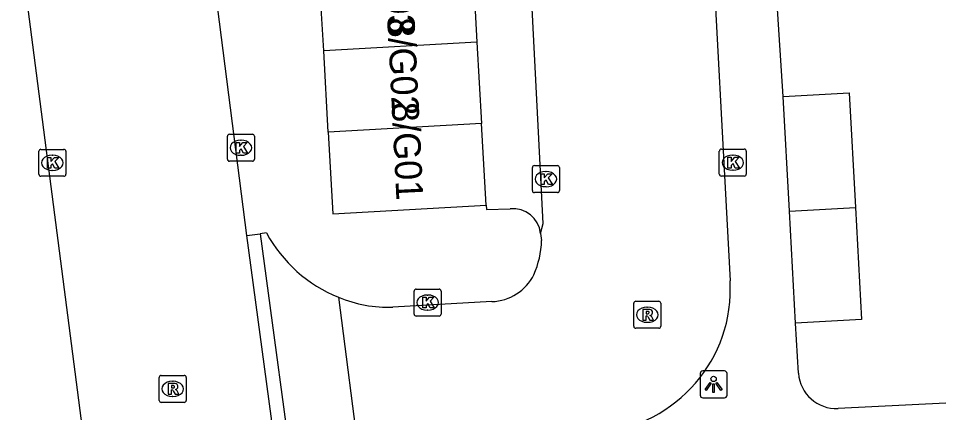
# Model space of a CAD drawing. Extents: x 161084 to 161928, y 385355 to 386522.
# Drawn here: x 161311.4 to 161345.53, y 385480.77 to 385495.38 of the extents above; entities that cross this region are included whole.
import ezdxf

# ---------------------------------------------------------------- set-up
doc = ezdxf.new("R2010")
doc.units = 0
for name, color, linetype in [('IMGEO_Kolk', 7, 'Continuous'), ('IMGEO_Lichtpunt', 7, 'Continuous'), ('IMGEO_Pand', 7, 'Continuous'), ('IMGEO_Pand_nummerreeks', 7, 'Continuous'), ('IMGEO_Rijbaan_lokaal_open', 7, 'Continuous'), ('IMGEO_Rioolput', 7, 'Continuous'), ('IMGEO_Voetpad_open', 7, 'Continuous')]:
    doc.layers.add(name, color=color, linetype=linetype)

msp = doc.modelspace()

# ---------------------------------------------------------------- linework, layer by layer
at = {"layer": 'IMGEO_Kolk'}
for p, q in [((161319.152, 385490.161), (161319.152, 385491.013)), ((161319.227, 385491.087), (161320.079, 385491.087)), ((161320.153, 385491.013), (161320.153, 385490.161)), ((161319.64, 385490.867), (161319.665, 385490.867)), ((161312.159, 385489.602), (161312.159, 385490.454)), ((161312.234, 385490.528), (161313.086, 385490.528)), ((161312.647, 385490.308), (161312.672, 385490.308)), ((161313.16, 385490.454), (161313.16, 385489.602)), ((161319.663, 385490.307), (161319.638, 385490.307)), ((161337.399, 385489.608), (161337.399, 385490.46)), ((161337.474, 385490.534), (161338.326, 385490.534)), ((161337.887, 385490.314), (161337.912, 385490.314)), ((161338.4, 385490.46), (161338.4, 385489.608)), ((161320.079, 385490.087), (161319.227, 385490.087)), ((161330.539, 385489.924), (161331.391, 385489.924)), ((161312.67, 385489.748), (161312.645, 385489.748)), ((161330.464, 385488.998), (161330.464, 385489.85)), ((161330.952, 385489.704), (161330.977, 385489.704)), ((161331.465, 385489.85), (161331.465, 385488.998)), ((161337.91, 385489.754), (161337.885, 385489.754)), ((161313.086, 385489.528), (161312.234, 385489.528)), ((161338.326, 385489.534), (161337.474, 385489.534)), ((161331.391, 385488.924), (161330.539, 385488.924)), ((161330.975, 385489.144), (161330.95, 385489.144)), ((161326.077, 385484.422), (161326.077, 385485.274)), ((161326.152, 385485.348), (161327.004, 385485.348)), ((161326.565, 385485.128), (161326.59, 385485.128)), ((161327.078, 385485.274), (161327.078, 385484.422)), ((161326.588, 385484.568), (161326.563, 385484.568)), ((161327.004, 385484.348), (161326.152, 385484.348))]:
    msp.add_line(p, q, dxfattribs=at)
for points in [[(161319.152, 385490.161), (161319.152, 385491.013)], [(161319.227, 385491.087), (161320.079, 385491.087)], [(161320.153, 385491.013), (161320.153, 385490.161)], [(161319.473, 385490.787), (161319.596, 385490.787), (161319.596, 385490.636), (161319.726, 385490.787), (161319.89, 385490.787), (161319.744, 385490.636), (161319.897, 385490.387), (161319.745, 385490.387), (161319.66, 385490.551), (161319.596, 385490.484), (161319.596, 385490.387), (161319.473, 385490.387), (161319.473, 385490.787)], [(161312.159, 385489.602), (161312.159, 385490.454)], [(161312.234, 385490.528), (161313.086, 385490.528)], [(161313.16, 385490.454), (161313.16, 385489.602)], [(161337.399, 385489.608), (161337.399, 385490.46)], [(161337.474, 385490.534), (161338.326, 385490.534)], [(161337.72, 385490.234), (161337.843, 385490.234), (161337.843, 385490.083), (161337.973, 385490.234), (161338.137, 385490.234), (161337.991, 385490.083), (161338.144, 385489.834), (161337.992, 385489.834), (161337.907, 385489.998), (161337.843, 385489.931), (161337.843, 385489.834), (161337.72, 385489.834), (161337.72, 385490.234)], [(161338.4, 385490.46), (161338.4, 385489.608)], [(161312.48, 385490.228), (161312.603, 385490.228), (161312.603, 385490.077), (161312.733, 385490.228), (161312.897, 385490.228), (161312.751, 385490.077), (161312.904, 385489.828), (161312.752, 385489.828), (161312.667, 385489.992), (161312.603, 385489.925), (161312.603, 385489.828), (161312.48, 385489.828), (161312.48, 385490.228)], [(161320.079, 385490.087), (161319.227, 385490.087)], [(161330.539, 385489.924), (161331.391, 385489.924)], [(161330.464, 385488.998), (161330.464, 385489.85)], [(161330.785, 385489.624), (161330.908, 385489.624), (161330.908, 385489.473), (161331.038, 385489.624), (161331.202, 385489.624), (161331.056, 385489.473), (161331.209, 385489.224), (161331.057, 385489.224), (161330.972, 385489.388), (161330.908, 385489.321), (161330.908, 385489.224), (161330.785, 385489.224), (161330.785, 385489.624)], [(161331.465, 385489.85), (161331.465, 385488.998)], [(161313.086, 385489.528), (161312.234, 385489.528)], [(161338.326, 385489.534), (161337.474, 385489.534)], [(161331.391, 385488.924), (161330.539, 385488.924)], [(161326.077, 385484.422), (161326.077, 385485.274)], [(161326.152, 385485.348), (161327.004, 385485.348)], [(161327.078, 385485.274), (161327.078, 385484.422)], [(161326.398, 385485.048), (161326.521, 385485.048), (161326.521, 385484.897), (161326.651, 385485.048), (161326.815, 385485.048), (161326.669, 385484.897), (161326.822, 385484.648), (161326.67, 385484.648), (161326.585, 385484.812), (161326.521, 385484.745), (161326.521, 385484.648), (161326.398, 385484.648), (161326.398, 385485.048)], [(161327.004, 385484.348), (161326.152, 385484.348)]]:
    msp.add_lwpolyline(points, dxfattribs=at)
for centre, start, end in [((161319.229, 385491.011), 91.552, 178.448), ((161319.229, 385491.011), 91.552, 178.448), ((161320.077, 385491.011), 1.552, 88.448), ((161320.077, 385491.011), 1.552, 88.448), ((161312.236, 385490.452), 91.552, 178.448), ((161312.236, 385490.452), 91.552, 178.448), ((161313.084, 385490.452), 1.552, 88.448), ((161313.084, 385490.452), 1.552, 88.448), ((161337.476, 385490.458), 91.552, 178.448), ((161337.476, 385490.458), 91.552, 178.448), ((161338.324, 385490.458), 1.552, 88.448), ((161338.324, 385490.458), 1.552, 88.448), ((161319.229, 385490.163), 181.552, 268.448), ((161319.229, 385490.163), 181.552, 268.448), ((161320.077, 385490.163), 271.552, 358.448), ((161320.077, 385490.163), 271.552, 358.448), ((161330.541, 385489.848), 91.552, 178.448), ((161330.541, 385489.848), 91.552, 178.448), ((161331.389, 385489.848), 1.552, 88.448), ((161331.389, 385489.848), 1.552, 88.448), ((161312.236, 385489.604), 181.552, 268.448), ((161312.236, 385489.604), 181.552, 268.448), ((161313.084, 385489.604), 271.552, 358.448), ((161313.084, 385489.604), 271.552, 358.448), ((161337.476, 385489.61), 181.552, 268.448), ((161337.476, 385489.61), 181.552, 268.448), ((161338.324, 385489.61), 271.552, 358.448), ((161338.324, 385489.61), 271.552, 358.448), ((161330.541, 385489), 181.552, 268.448), ((161330.541, 385489), 181.552, 268.448), ((161331.389, 385489), 271.552, 358.448), ((161331.389, 385489), 271.552, 358.448), ((161326.154, 385485.272), 91.552, 178.448), ((161326.154, 385485.272), 91.552, 178.448), ((161327.002, 385485.272), 1.552, 88.448), ((161327.002, 385485.272), 1.552, 88.448), ((161326.154, 385484.424), 181.552, 268.448), ((161326.154, 385484.424), 181.552, 268.448), ((161327.002, 385484.424), 271.552, 358.448), ((161327.002, 385484.424), 271.552, 358.448)]:
    msp.add_arc(centre, 0.0765, start, end, dxfattribs=at)
for centre, major_axis, ratio, start_param, end_param in [((161319.639, 385490.587), (-0.387, 0.002), 0.722429, 4.712389, 7.853982), ((161319.664, 385490.587), (-0.39, 0.002), 0.717154, 1.570796, 4.712389), ((161312.646, 385490.028), (-0.387, 0.002), 0.722429, 4.712389, 7.853982), ((161312.671, 385490.028), (-0.39, 0.002), 0.717154, 1.570796, 4.712389), ((161337.886, 385490.034), (-0.387, 0.002), 0.722429, 4.712389, 7.853982), ((161337.911, 385490.034), (-0.39, 0.002), 0.717154, 1.570796, 4.712389), ((161330.951, 385489.424), (-0.387, 0.002), 0.722429, 4.712389, 7.853982), ((161330.976, 385489.424), (-0.39, 0.002), 0.717154, 1.570796, 4.712389), ((161326.564, 385484.848), (-0.387, 0.002), 0.722429, 4.712389, 7.853982), ((161326.589, 385484.848), (-0.39, 0.002), 0.717154, 1.570796, 4.712389)]:
    msp.add_ellipse(centre, major_axis=major_axis, ratio=ratio, start_param=start_param, end_param=end_param, dxfattribs=at)
at = {"layer": 'IMGEO_Lichtpunt'}
for p, q in [((161336.688, 385482.22), (161336.688, 385481.413)), ((161336.688, 385482.22), (161336.688, 385481.413)), ((161337.59, 385482.315), (161336.782, 385482.315)), ((161337.59, 385482.315), (161336.782, 385482.315)), ((161337.684, 385481.413), (161337.684, 385482.22)), ((161337.684, 385481.413), (161337.684, 385482.22)), ((161336.782, 385481.319), (161337.59, 385481.319)), ((161336.782, 385481.319), (161337.59, 385481.319))]:
    msp.add_line(p, q, dxfattribs=at)
for points in [[(161337.062, 385481.884), (161337.101, 385481.856), (161336.913, 385481.594), (161336.875, 385481.621), (161337.062, 385481.884)], [(161337.164, 385481.836), (161337.211, 385481.836), (161337.211, 385481.514), (161337.164, 385481.514), (161337.164, 385481.836)], [(161337.274, 385481.856), (161337.312, 385481.883), (161337.499, 385481.621), (161337.46, 385481.593), (161337.274, 385481.856)]]:
    msp.add_lwpolyline(points, dxfattribs=at)
msp.add_circle((161337.187, 385482.018), 0.0994, dxfattribs=at)
for centre, start, end in [((161336.782, 385482.22), 90, 180), ((161336.782, 385482.22), 90, 180), ((161337.59, 385482.22), 0, 90), ((161337.59, 385482.22), 0, 90), ((161336.782, 385481.413), 180, 270), ((161336.782, 385481.413), 180, 270), ((161337.59, 385481.413), 270, 0), ((161337.59, 385481.413), 270, 360)]:
    msp.add_arc(centre, 0.0946, start, end, dxfattribs=at)
at = {"layer": 'IMGEO_Pand'}
for points in [[(161328.238, 385497.524), (161328.409, 385494.502)], [(161322.723, 385494.18), (161322.622, 385495.956)], [(161328.409, 385494.502), (161322.723, 385494.18)], [(161328.409, 385494.502), (161328.58, 385491.48)], [(161322.896, 385491.159), (161322.723, 385494.18)], [(161339.771, 385492.485), (161342.219, 385492.618), (161342.45, 385488.367)], [(161340.002, 385488.233), (161339.771, 385492.485)], [(161328.58, 385491.48), (161322.896, 385491.159)], [(161328.751, 385488.458), (161328.58, 385491.48)], [(161322.896, 385491.159), (161323.068, 385488.134), (161328.751, 385488.458)], [(161340.002, 385488.233), (161342.45, 385488.367)], [(161340.227, 385484.085), (161340.002, 385488.233)], [(161342.45, 385488.367), (161342.675, 385484.218), (161340.227, 385484.085)]]:
    msp.add_lwpolyline(points, dxfattribs=at)
at = {"layer": 'IMGEO_Rijbaan_lokaal_open'}
for points in [[(161335.42, 385532.391), (161337.024, 385500.143), (161337.796, 385485.654)], [(161330.768, 385487.413), (161330.865, 385487.775), (161328.687, 385530.316), (161328.582, 385530.386)], [(161319.868, 385487.335), (161318.329, 385499.414)], [(161315.293, 385468.442), (161311.4, 385498.51)], [(161321.269, 385476.973), (161319.868, 385487.335)], [(161320.606, 385487.429), (161320.363, 385487.4)], [(161320.363, 385487.4), (161321.764, 385477.038)], [(161330.768, 385487.413), (161330.809, 385487.145)], [(161323.275, 385485.049), (161324.075, 385478.793)], [(161328.966, 385484.883), (161325.294, 385484.679)]]:
    msp.add_lwpolyline(points, dxfattribs=at)
for centre, radius, start, end in [((161325.199, 385489.894), 5.213, 208.2161, 248.3358), ((161327.198, 385487.298), 3.614, 336.9229, 357.5783), ((161328.897, 385486.705), 1.823, 272.1835, 333.1343), ((161332.497, 385485.334), 5.309, 274.8736, 3.4611), ((161325.114, 385489.39), 4.714, 247.0411, 272.1895)]:
    msp.add_arc(centre, radius, start, end, dxfattribs=at)
at = {"layer": 'IMGEO_Rioolput'}
for p, q in [((161334.227, 385483.97), (161334.227, 385484.822)), ((161334.302, 385484.896), (161335.154, 385484.896)), ((161335.228, 385484.822), (161335.228, 385483.97)), ((161334.715, 385484.676), (161334.74, 385484.676)), ((161334.738, 385484.116), (161334.713, 385484.116)), ((161335.154, 385483.896), (161334.302, 385483.896)), ((161316.623, 385481.224), (161316.623, 385482.076)), ((161316.698, 385482.15), (161317.55, 385482.15)), ((161317.624, 385482.076), (161317.624, 385481.224)), ((161317.111, 385481.93), (161317.136, 385481.93)), ((161317.134, 385481.37), (161317.109, 385481.37)), ((161317.55, 385481.15), (161316.698, 385481.15))]:
    msp.add_line(p, q, dxfattribs=at)
for points in [[(161334.227, 385483.97), (161334.227, 385484.822)], [(161334.302, 385484.896), (161335.154, 385484.896)], [(161335.228, 385484.822), (161335.228, 385483.97)], [(161334.816, 385484.594), (161334.564, 385484.596), (161334.564, 385484.196)], [(161334.742, 385484.515), (161334.688, 385484.515), (161334.688, 385484.434)], [(161334.688, 385484.434), (161334.74, 385484.434)], [(161334.564, 385484.196), (161334.688, 385484.196), (161334.688, 385484.358), (161334.699, 385484.358)], [(161334.746, 385484.329), (161334.817, 385484.196), (161334.957, 385484.196), (161334.892, 385484.322)], [(161335.154, 385483.896), (161334.302, 385483.896)], [(161316.623, 385481.224), (161316.623, 385482.076)], [(161316.698, 385482.15), (161317.55, 385482.15)], [(161317.624, 385482.076), (161317.624, 385481.224)], [(161317.212, 385481.848), (161316.96, 385481.85), (161316.96, 385481.45)], [(161317.138, 385481.769), (161317.084, 385481.769), (161317.084, 385481.688)], [(161316.96, 385481.45), (161317.084, 385481.45), (161317.084, 385481.612), (161317.095, 385481.612)], [(161317.084, 385481.688), (161317.136, 385481.688)], [(161317.142, 385481.583), (161317.213, 385481.45), (161317.353, 385481.45), (161317.288, 385481.576)], [(161317.55, 385481.15), (161316.698, 385481.15)]]:
    msp.add_lwpolyline(points, dxfattribs=at)
for centre, radius, start, end in [((161334.304, 385484.82), 0.0765, 91.552, 178.448), ((161334.304, 385484.82), 0.0765, 91.552, 178.448), ((161335.152, 385484.82), 0.0765, 1.552, 88.448), ((161335.152, 385484.82), 0.0765, 1.552, 88.448), ((161334.724, 385484.623), 0.19, 274.7715, 282.9687), ((161334.748, 385484.419), 0.0964, 77.0061, 93.1865), ((161334.762, 385484.476), 0.0378, 276.6634, 79.6772), ((161334.815, 385484.484), 0.109, 350.3612, 89.416), ((161334.813, 385484.484), 0.112, 277.5842, 350.9817), ((161334.698, 385484.305), 0.0533, 26.0293, 88.6989), ((161334.797, 385484.269), 0.108, 29.5134, 73.7905), ((161334.304, 385483.972), 0.0765, 181.552, 268.448), ((161334.304, 385483.972), 0.0765, 181.552, 268.448), ((161335.152, 385483.972), 0.0765, 271.552, 358.448), ((161335.152, 385483.972), 0.0765, 271.552, 358.448), ((161316.7, 385482.074), 0.0765, 91.552, 178.448), ((161316.7, 385482.074), 0.0765, 91.552, 178.448), ((161317.548, 385482.074), 0.0765, 1.552, 88.448), ((161317.548, 385482.074), 0.0765, 1.552, 88.448), ((161317.144, 385481.673), 0.0964, 77.0061, 93.1865), ((161317.158, 385481.73), 0.0378, 276.6634, 79.6772), ((161317.211, 385481.738), 0.109, 350.3612, 89.416), ((161317.209, 385481.738), 0.112, 277.5842, 350.9817), ((161317.094, 385481.559), 0.0533, 26.0293, 88.6989), ((161317.12, 385481.877), 0.19, 274.7715, 282.9687), ((161317.193, 385481.523), 0.108, 29.5134, 73.7905), ((161316.7, 385481.226), 0.0765, 181.552, 268.448), ((161316.7, 385481.226), 0.0765, 181.552, 268.448), ((161317.548, 385481.226), 0.0765, 271.552, 358.448), ((161317.548, 385481.226), 0.0765, 271.552, 358.448)]:
    msp.add_arc(centre, radius, start, end, dxfattribs=at)
for centre, major_axis, ratio, start_param, end_param in [((161334.714, 385484.396), (-0.387, 0.002), 0.722429, 4.712389, 7.853982), ((161334.739, 385484.396), (-0.39, 0.002), 0.717154, 1.570796, 4.712389), ((161317.11, 385481.65), (-0.387, 0.002), 0.722429, 4.712389, 7.853982), ((161317.135, 385481.65), (-0.39, 0.002), 0.717154, 1.570796, 4.712389)]:
    msp.add_ellipse(centre, major_axis=major_axis, ratio=ratio, start_param=start_param, end_param=end_param, dxfattribs=at)
at = {"layer": 'IMGEO_Voetpad_open'}
for points in [[(161339.771, 385492.485), (161339.535, 385496.121)], [(161328.751, 385488.458), (161328.763, 385488.294), (161329.639, 385488.318)], [(161319.868, 385487.335), (161320.363, 385487.4)], [(161340.331, 385482.228), (161340.227, 385484.085)], [(161361.528, 385481.899), (161341.805, 385480.919)]]:
    msp.add_lwpolyline(points, dxfattribs=at)
for centre, radius, start, end in [((161329.751, 385487.3), 1.024, 6.3129, 96.2562), ((161341.747, 385482.338), 1.42, 184.4419, 272.3441)]:
    msp.add_arc(centre, radius, start, end, dxfattribs=at)

# ---------------------------------------------------------------- texts
at = {"layer": 'IMGEO_Pand_nummerreeks'}
for s, p in [('8/G03', (161324.935, 385498.406)), ('8/G02', (161325.085, 385495.392)), ('8/G01', (161325.242, 385492.255))]:
    msp.add_text(s, height=1, rotation=272.8562, dxfattribs=at).set_placement(p)

doc.saveas('drawing.dxf')
